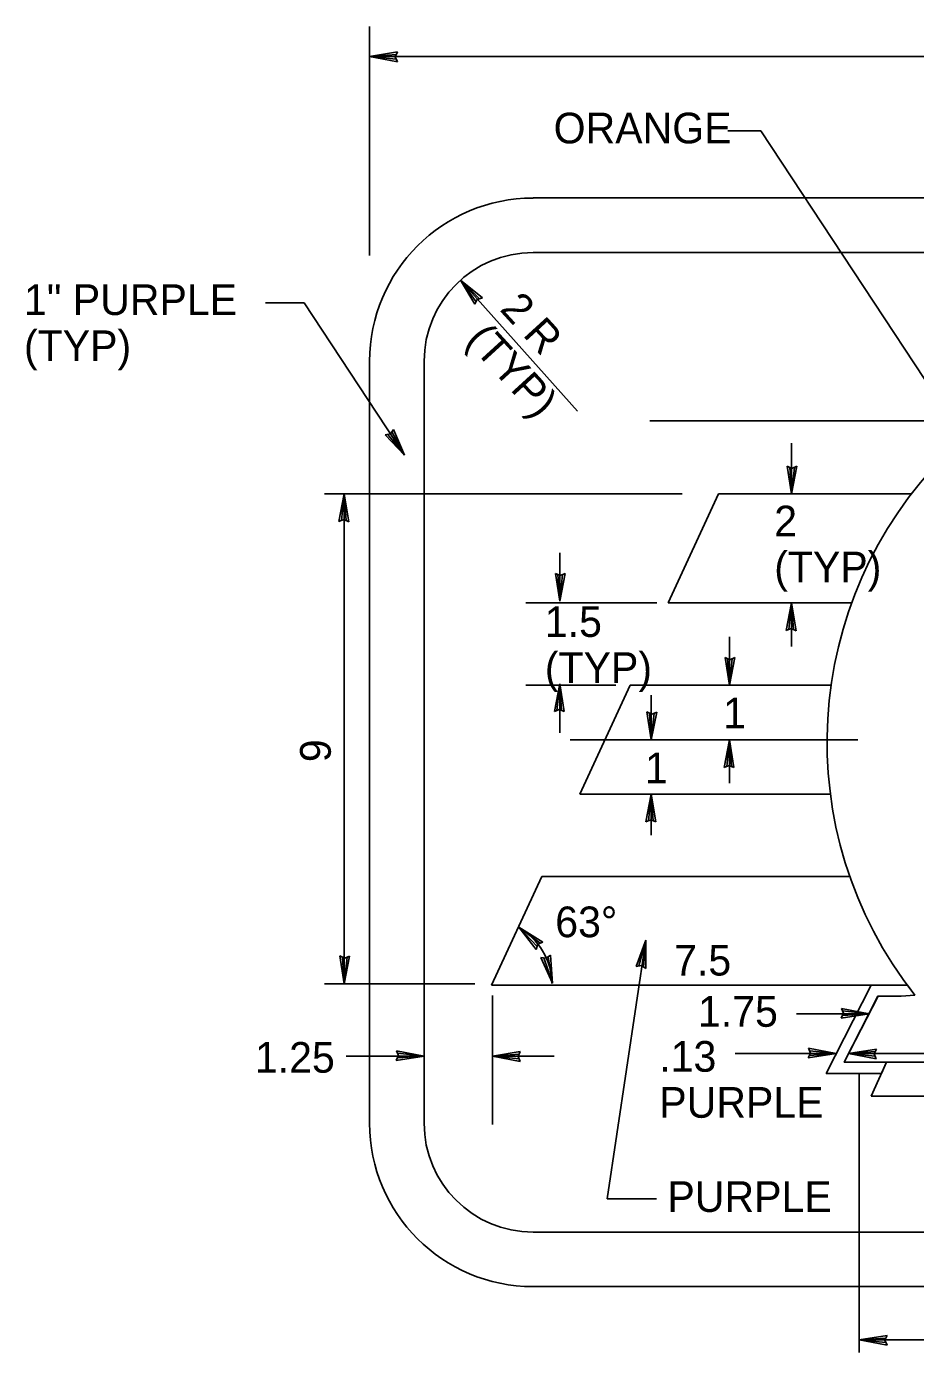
# Model space of a CAD drawing. Extents: x 10268197 to 10269179, y 2141503 to 2142677.
# Drawn here: x 10268767.13 to 10268787.54, y 2142159.16 to 2142189.61 of the extents above; entities that cross this region are included whole.
import ezdxf

# ---------------------------------------------------------------- set-up
doc = ezdxf.new("R2010")
doc.units = 0
for name, color, linetype in [('1', 7, 'Continuous'), ('Default', 7, 'Continuous'), ('TextMisc', 7, 'Continuous'), ('TextShtNo', 7, 'Continuous')]:
    doc.layers.add(name, color=color, linetype=linetype)

msp = doc.modelspace()

# ---------------------------------------------------------------- linework, layer by layer
at = {"layer": '1'}
for p, q in [((10268777.095, 2142183.789), (10268779.78, 2142180.781)), ((10268781.352, 2142168.63), (10268780.463, 2142162.691)), ((10268786.757, 2142165.57), (10268785.49, 2142165.57)), ((10268780.463, 2142162.691), (10268781.596, 2142162.691))]:
    msp.add_line(p, q, dxfattribs=at)
msp.add_ellipse((10268777.702, 2142167.614), major_axis=(0, 1.49), ratio=0.999997, start_param=4.726798, end_param=5.778675, dxfattribs=at)
at = {"layer": 'Default'}
for p, q in [((10268775.009, 2142188.927), (10268775.649, 2142189.029)), ((10268775.009, 2142188.927), (10268775.622, 2142188.971)), ((10268775.009, 2142188.927), (10268807.509, 2142188.927)), ((10268775.009, 2142188.927), (10268775.645, 2142188.804)), ((10268775.009, 2142188.927), (10268775.621, 2142188.863)), ((10268775.598, 2142188.917), (10268775.649, 2142189.029)), ((10268775.645, 2142188.804), (10268775.598, 2142188.917)), ((10268783.234, 2142187.214), (10268783.991, 2142187.214)), ((10268783.991, 2142187.214), (10268789.101, 2142179.449)), ((10268778.76, 2142184.424), (10268803.759, 2142184.424)), ((10268777.095, 2142183.789), (10268777.596, 2142183.379)), ((10268777.095, 2142183.789), (10268777.426, 2142183.233)), ((10268777.095, 2142183.789), (10268777.454, 2142183.29)), ((10268777.095, 2142183.789), (10268777.534, 2142183.361)), ((10268777.426, 2142183.233), (10268777.479, 2142183.343)), ((10268777.479, 2142183.343), (10268777.596, 2142183.379)), ((10268772.62, 2142183.263), (10268773.508, 2142183.263)), ((10268773.508, 2142183.263), (10268775.81, 2142179.764)), ((10268776.259, 2142164.424), (10268776.259, 2142181.923)), ((10268775.554, 2142180.359), (10268775.487, 2142180.256)), ((10268775.81, 2142179.764), (10268775.518, 2142180.306)), ((10268775.81, 2142179.764), (10268775.554, 2142180.359)), ((10268781.437, 2142180.557), (10268792.774, 2142180.557)), ((10268775.487, 2142180.256), (10268775.366, 2142180.236)), ((10268775.81, 2142179.764), (10268775.366, 2142180.236)), ((10268775.81, 2142179.764), (10268775.429, 2142180.246)), ((10268784.693, 2142180.045), (10268784.693, 2142178.876)), ((10268784.693, 2142178.876), (10268784.592, 2142179.516)), ((10268784.703, 2142179.465), (10268784.592, 2142179.516)), ((10268784.693, 2142178.876), (10268784.65, 2142179.489)), ((10268784.693, 2142178.876), (10268784.816, 2142179.512)), ((10268784.693, 2142178.876), (10268784.757, 2142179.488)), ((10268784.816, 2142179.512), (10268784.703, 2142179.465)), ((10268773.974, 2142178.876), (10268782.181, 2142178.876)), ((10268774.427, 2142178.876), (10268774.304, 2142178.241)), ((10268774.427, 2142178.876), (10268774.363, 2142178.265)), ((10268774.427, 2142178.876), (10268774.427, 2142167.626)), ((10268774.427, 2142178.876), (10268774.528, 2142178.237)), ((10268774.427, 2142178.876), (10268774.47, 2142178.264)), ((10268783.018, 2142178.876), (10268781.863, 2142176.377)), ((10268787.443, 2142178.876), (10268783.018, 2142178.876)), ((10268774.304, 2142178.241), (10268774.417, 2142178.288)), ((10268774.417, 2142178.288), (10268774.528, 2142178.237)), ((10268779.373, 2142177.521), (10268779.373, 2142176.413)), ((10268779.373, 2142176.413), (10268779.271, 2142177.052)), ((10268779.383, 2142177.001), (10268779.271, 2142177.052)), ((10268779.373, 2142176.413), (10268779.33, 2142177.025)), ((10268779.373, 2142176.413), (10268779.496, 2142177.048)), ((10268779.373, 2142176.413), (10268779.436, 2142177.024)), ((10268779.496, 2142177.048), (10268779.383, 2142177.001)), ((10268778.593, 2142176.377), (10268781.599, 2142176.377)), ((10268786.073, 2142176.377), (10268781.863, 2142176.377)), ((10268784.693, 2142176.377), (10268784.57, 2142175.741)), ((10268784.693, 2142176.377), (10268784.629, 2142175.765)), ((10268784.693, 2142176.377), (10268784.693, 2142175.371)), ((10268784.693, 2142176.377), (10268784.795, 2142175.737)), ((10268784.693, 2142176.377), (10268784.736, 2142175.764)), ((10268784.57, 2142175.741), (10268784.683, 2142175.788)), ((10268784.683, 2142175.788), (10268784.795, 2142175.737)), ((10268783.269, 2142175.599), (10268783.269, 2142174.483)), ((10268783.269, 2142174.483), (10268783.167, 2142175.122)), ((10268783.279, 2142175.071), (10268783.167, 2142175.122)), ((10268783.269, 2142174.483), (10268783.392, 2142175.118)), ((10268783.392, 2142175.118), (10268783.279, 2142175.071)), ((10268783.269, 2142174.483), (10268783.226, 2142175.095)), ((10268783.269, 2142174.483), (10268783.333, 2142175.094)), ((10268779.373, 2142174.517), (10268779.25, 2142173.882)), ((10268779.373, 2142174.517), (10268779.309, 2142173.906)), ((10268779.373, 2142174.517), (10268779.373, 2142173.388)), ((10268779.373, 2142174.517), (10268779.474, 2142173.878)), ((10268779.373, 2142174.517), (10268779.416, 2142173.905)), ((10268778.593, 2142174.483), (10268780.66, 2142174.483)), ((10268780.989, 2142174.483), (10268779.834, 2142171.983)), ((10268785.601, 2142174.483), (10268780.989, 2142174.483)), ((10268781.474, 2142174.259), (10268781.474, 2142173.233)), ((10268779.25, 2142173.882), (10268779.362, 2142173.929)), ((10268779.362, 2142173.929), (10268779.474, 2142173.878)), ((10268781.474, 2142173.233), (10268781.373, 2142173.872)), ((10268781.484, 2142173.822), (10268781.373, 2142173.872)), ((10268781.474, 2142173.233), (10268781.431, 2142173.845)), ((10268781.474, 2142173.233), (10268781.597, 2142173.868)), ((10268781.474, 2142173.233), (10268781.538, 2142173.844)), ((10268781.597, 2142173.868), (10268781.484, 2142173.822)), ((10268779.614, 2142173.233), (10268786.211, 2142173.233)), ((10268783.269, 2142173.233), (10268783.146, 2142172.597)), ((10268783.269, 2142173.233), (10268783.205, 2142172.621)), ((10268783.269, 2142173.233), (10268783.269, 2142172.236)), ((10268783.269, 2142173.233), (10268783.37, 2142172.593)), ((10268783.269, 2142173.233), (10268783.312, 2142172.62)), ((10268783.146, 2142172.597), (10268783.259, 2142172.644)), ((10268783.259, 2142172.644), (10268783.37, 2142172.593)), ((10268785.586, 2142171.983), (10268779.834, 2142171.983)), ((10268781.474, 2142171.983), (10268781.351, 2142171.347)), ((10268781.474, 2142171.983), (10268781.41, 2142171.371)), ((10268781.474, 2142171.983), (10268781.474, 2142171.039)), ((10268781.474, 2142171.983), (10268781.575, 2142171.343)), ((10268781.474, 2142171.983), (10268781.517, 2142171.37)), ((10268781.351, 2142171.347), (10268781.464, 2142171.394)), ((10268781.464, 2142171.394), (10268781.575, 2142171.343)), ((10268778.959, 2142170.088), (10268777.809, 2142167.599)), ((10268786.008, 2142170.088), (10268778.959, 2142170.088)), ((10268778.431, 2142168.928), (10268778.981, 2142168.586)), ((10268778.431, 2142168.928), (10268778.831, 2142168.418)), ((10268778.431, 2142168.928), (10268778.851, 2142168.48)), ((10268778.431, 2142168.928), (10268778.922, 2142168.56)), ((10268778.831, 2142168.418), (10268778.869, 2142168.535)), ((10268778.869, 2142168.535), (10268778.981, 2142168.586)), ((10268781.352, 2142168.63), (10268781.126, 2142168.023)), ((10268781.352, 2142168.63), (10268781.189, 2142168.038)), ((10268781.352, 2142168.63), (10268781.294, 2142168.019)), ((10268781.352, 2142168.63), (10268781.347, 2142167.982)), ((10268774.427, 2142167.626), (10268774.326, 2142168.266)), ((10268774.437, 2142168.215), (10268774.326, 2142168.266)), ((10268774.427, 2142167.626), (10268774.384, 2142168.239)), ((10268774.427, 2142167.626), (10268774.55, 2142168.262)), ((10268774.427, 2142167.626), (10268774.49, 2142168.238)), ((10268774.55, 2142168.262), (10268774.437, 2142168.215)), ((10268779.203, 2142167.639), (10268778.941, 2142168.232)), ((10268779.062, 2142168.212), (10268778.941, 2142168.232)), ((10268779.203, 2142167.639), (10268779.005, 2142168.221)), ((10268779.16, 2142168.286), (10268779.062, 2142168.212)), ((10268779.203, 2142167.639), (10268779.108, 2142168.246)), ((10268779.203, 2142167.639), (10268779.16, 2142168.286)), ((10268781.126, 2142168.023), (10268781.245, 2142168.05)), ((10268781.245, 2142168.05), (10268781.347, 2142167.982)), ((10268773.974, 2142167.626), (10268777.423, 2142167.626)), ((10268777.809, 2142167.599), (10268787.327, 2142167.599)), ((10268786.522, 2142167.599), (10268785.49, 2142165.57)), ((10268786.522, 2142167.599), (10268787.351, 2142167.599)), ((10268777.828, 2142167.362), (10268777.828, 2142164.398)), ((10268786.677, 2142167.344), (10268785.904, 2142165.824)), ((10268786.678, 2142167.344), (10268787.211, 2142167.344)), ((10268787.211, 2142167.344), (10268787.522, 2142167.369)), ((10268784.804, 2142166.94), (10268786.472, 2142166.94)), ((10268785.883, 2142166.95), (10268785.832, 2142166.839)), ((10268786.472, 2142166.94), (10268785.832, 2142166.839)), ((10268786.472, 2142166.94), (10268785.836, 2142167.063)), ((10268785.836, 2142167.063), (10268785.883, 2142166.95)), ((10268786.472, 2142166.94), (10268785.86, 2142167.004)), ((10268786.472, 2142166.94), (10268785.86, 2142166.897)), ((10268774.47, 2142165.968), (10268776.259, 2142165.968)), ((10268775.671, 2142165.978), (10268775.62, 2142165.867)), ((10268776.259, 2142165.968), (10268775.62, 2142165.867)), ((10268776.259, 2142165.968), (10268775.624, 2142166.091)), ((10268775.624, 2142166.091), (10268775.671, 2142165.978)), ((10268776.259, 2142165.968), (10268775.647, 2142165.925)), ((10268776.259, 2142165.968), (10268775.648, 2142166.032)), ((10268777.828, 2142165.968), (10268778.467, 2142166.069)), ((10268777.828, 2142165.968), (10268778.44, 2142166.011)), ((10268777.828, 2142165.968), (10268779.244, 2142165.968)), ((10268777.828, 2142165.968), (10268778.463, 2142165.845)), ((10268777.828, 2142165.968), (10268778.439, 2142165.904)), ((10268778.417, 2142165.958), (10268778.467, 2142166.069)), ((10268783.397, 2142166.026), (10268785.717, 2142166.026)), ((10268785.128, 2142166.035), (10268785.077, 2142165.925)), ((10268785.717, 2142166.026), (10268785.077, 2142165.925)), ((10268785.717, 2142166.026), (10268785.081, 2142166.149)), ((10268785.081, 2142166.149), (10268785.128, 2142166.035)), ((10268785.717, 2142166.026), (10268785.105, 2142165.983)), ((10268785.717, 2142166.026), (10268785.106, 2142166.089)), ((10268786.001, 2142166.026), (10268786.641, 2142166.127)), ((10268786.001, 2142166.026), (10268786.614, 2142166.069)), ((10268786.001, 2142166.026), (10268787.909, 2142166.026)), ((10268786.001, 2142166.026), (10268786.637, 2142165.903)), ((10268786.001, 2142166.026), (10268786.612, 2142165.962)), ((10268786.59, 2142166.015), (10268786.641, 2142166.127)), ((10268786.637, 2142165.903), (10268786.59, 2142166.015)), ((10268778.463, 2142165.845), (10268778.417, 2142165.958)), ((10268785.904, 2142165.824), (10268786.998, 2142165.824)), ((10268786.517, 2142165.048), (10268786.874, 2142165.824)), ((10268798.123, 2142165.824), (10268786.874, 2142165.824)), ((10268786.248, 2142159.16), (10268786.248, 2142165.582)), ((10268798.817, 2142165.048), (10268786.517, 2142165.048)), ((10268778.76, 2142161.924), (10268803.759, 2142161.924)), ((10268786.248, 2142159.45), (10268786.887, 2142159.55)), ((10268786.248, 2142159.45), (10268786.861, 2142159.492)), ((10268786.248, 2142159.45), (10268798.123, 2142159.45)), ((10268786.248, 2142159.45), (10268786.884, 2142159.327)), ((10268786.248, 2142159.45), (10268786.859, 2142159.386)), ((10268786.837, 2142159.44), (10268786.887, 2142159.55)), ((10268786.884, 2142159.327), (10268786.837, 2142159.44))]:
    msp.add_line(p, q, dxfattribs=at)
for centre, major_axis, start_param, end_param in [((10268778.759, 2142181.923), (0, 2.5), 0, 1.570796), ((10268794.884, 2142173.173), (0, 9.375), 5.619293, 8.52162), ((10268778.759, 2142164.423), (0, -2.5), 4.712389, 6.283185)]:
    msp.add_ellipse(centre, major_axis=major_axis, ratio=0.999997, start_param=start_param, end_param=end_param, dxfattribs=at)
at = {"layer": 'TextMisc'}
for p, q in [((10268775.009, 2142184.354), (10268775.009, 2142189.612)), ((10268778.76, 2142185.674), (10268803.759, 2142185.674)), ((10268775.009, 2142164.424), (10268775.009, 2142181.923)), ((10268778.76, 2142160.674), (10268803.759, 2142160.674))]:
    msp.add_line(p, q, dxfattribs=at)
for centre, major_axis, start_param, end_param in [((10268778.759, 2142181.923), (0, 3.75), 0, 1.570796), ((10268778.759, 2142164.423), (0, -3.75), 4.712389, 6.283185)]:
    msp.add_ellipse(centre, major_axis=major_axis, ratio=0.999998, start_param=start_param, end_param=end_param, dxfattribs=at)
at = {"layer": 'TextShtNo'}
for p, q in [((10268786.517, 2142165.048), (10268786.874, 2142165.824)), ((10268786.874, 2142165.824), (10268798.123, 2142165.824)), ((10268798.817, 2142165.048), (10268786.517, 2142165.048))]:
    msp.add_line(p, q, dxfattribs=at)
msp.add_lwpolyline([(10268787.351, 2142167.599), (10268786.522, 2142167.599), (10268785.49, 2142165.57), (10268786.757, 2142165.57), (10268786.874, 2142165.824), (10268785.904, 2142165.824), (10268786.678, 2142167.344), (10268787.211, 2142167.344), (10268787.522, 2142167.369)], close=True, dxfattribs=at)

# ---------------------------------------------------------------- texts
at = {"layer": '1'}
for s, height, p in [('ORANGE', 0.7047, (10268779.232, 2142186.928)), ('1" PURPLE', 0.7047, (10268767.075, 2142182.986)), ('(TYP)', 0.7047, (10268767.075, 2142181.928)), ('2', 0.705, (10268784.295, 2142177.903)), ('(TYP)', 0.7047, (10268784.295, 2142176.846)), ('1.5', 0.7047, (10268779.03, 2142175.594)), ('(TYP)', 0.7047, (10268779.03, 2142174.537)), ('1', 0.705, (10268783.122, 2142173.493)), ('1', 0.705, (10268781.328, 2142172.233)), ('63°', 0.7047, (10268779.269, 2142168.697)), ('7.5', 0.7047, (10268781.997, 2142167.817)), ('1.75', 0.7047, (10268782.545, 2142166.64)), ('1.25', 0.7047, (10268772.375, 2142165.585)), ('.13', 0.7047, (10268781.657, 2142165.608)), ('PURPLE', 0.7047, (10268781.657, 2142164.551)), ('PURPLE', 0.7047, (10268781.844, 2142162.388))]:
    msp.add_text(s, height=height, dxfattribs=at).set_placement(p)
for s, height, rotation, p in [('2 R', 0.7047, 312.435, (10268777.975, 2142183.105)), ('(TYP)', 0.7047, 312.435, (10268777.195, 2142182.392)), ('9', 0.705, 90, (10268774.117, 2142172.718))]:
    msp.add_text(s, height=height, rotation=rotation, dxfattribs=at).set_placement(p)

doc.saveas('drawing.dxf')
